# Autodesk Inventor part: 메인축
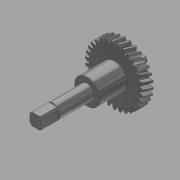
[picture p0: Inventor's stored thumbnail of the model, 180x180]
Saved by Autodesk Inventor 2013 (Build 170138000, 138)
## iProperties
Created: 2017-11
Part Number: 메인축
Material: 강철, 탄소
Document SubType Name: Modeling
Designer: mduedu
Categories: <?xml version="1.0" encoding="UTF-16"?> <MemberInstance><Categories><FamilyTemplate><FamilyTemplateParameter ValueType="xs:double" Id="1" ObjectReferenceKey="da
Density: 7.87 g/cm^3
Mass: 607.365 g
Surface Area: 183.17 cm^2
Volume: 77.1747 cm^3
CustomPartVersion: 1
Author: mduedu
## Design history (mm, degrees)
sketch "Sketch1"
  geometry: C1 r 34.094 at (0, 0)
  constraints: 1 centre point
  dimensions: "d0" = 68.18712 diameter of C1 (= da_da)
extrude "Extrusion1" new body sketch "Sketch1" distance "d1" = 12 (= da_b); taper "d2" = 0 deg
workplane "Work Plane2"
sketch "Sketch2"
  geometry: C1 r 34.094 at (0, 0) reference; C2 r 32.094 at (0, 0)
  constraints: 1 centre point, 1 coincident
  dimensions: "d3" = 64.18712 diameter of C2 (= da_dw)
feature "피치 지름" sketch "Sketch2" dims "d4" = 10, "d5" = 0
workplane "Work Plane8"
workplane "Work Plane9"
feature "스퍼 기어" dims "da_b" = 12, "da_d" = 64.18712, "da_aw" = 54.86964, "da_da" = 68.18712, "da_df" = 59.18712, "da_dw" = 64.18712, angle "da_beta" = 15 deg, "da_lefttooth" = 0, "da_righttooth" = 10
sketch "스케치3"
  geometry: C1 r 15 at (0, 0); 1 further point
  constraints: 1 centre point, 1 coincident
  dimensions: "d49" = 30 diameter of C1
extrude "돌출2" join sketch "스케치3" distance "d50" = 32; taper "d51" = 0 deg
sketch "스케치4"
  geometry: C1 r 8.5 at (0, 0); 1 further point
  constraints: 1 centre point, 1 coincident
  dimensions: "d52" = 17 diameter of C1
extrude "돌출3" join sketch "스케치4" distance "d53" = 60; taper "d54" = 0 deg
sketch "스케치5"
  geometry: C1 r 7.5 at (0, 0); 1 further point
  constraints: 1 centre point, 1 coincident
  dimensions: "d55" = 15 diameter of C1
extrude "돌출4" join sketch "스케치5" distance "d56" = 16; taper "d57" = 0 deg
sketch "스케치6"
  geometry: C1 r 4 at (0, 0); 1 further point
  constraints: 1 centre point, 1 coincident
  dimensions: "d58" = 8 diameter of C1
extrude "돌출5" join sketch "스케치6" distance "d59" = 7; taper "d60" = 0 deg
chamfer "모따기1" distance "d61" = 0.5; stored, may be unused: second distance "d62" = 2, angle "d63" = 45 deg
fillet "모깎기1" dims "d64" = 0.5
sketch "스케치7"
  geometry: L1 (-7, -7)-(7, -7); L2 (7, -7)-(7, 7); L3 (7, 7)-(-7, 7); L4 (-7, 7)-(-7, -7); L5 (-7, -7)-(7, 7); L6 (7, -7)-(-7, 7); L7 (-10, -10)-(10, -10); L8 (10, -10)-(10, 10); L9 (10, 10)-(-10, 10); L10 (-10, 10)-(-10, -10); L11 (-10, -10)-(10, 10); L12 (10, -10)-(-10, 10); 1 further point
  constraints: 24 end point, 4 midpoint, 4 parallel, 2 horizontal, 2 perpendicular
  dimensions: "d65" = 14 distance of L3.end L2.end; "d66" = 14 distance of L2.end L1.end; "d67" = 20 distance of L9.end L8.end; "d68" = 20 distance of L8.end L7.end
extrude "돌출6" cut sketch "스케치7" distance "d69" = 20; taper "d70" = 0 deg
body "Solid1"
body "Srf1"
other parameters: "d16" = 54.86964 (= da_aw), "d17" = 0, "d34" = 1.01342 (computed from da_z), "d39" = 0, "d41" = 0, "d43" = 54.86964 (= da_aw), "d46" = 54.86964 (= da_aw), "d47" = 0, "d48" = 0
